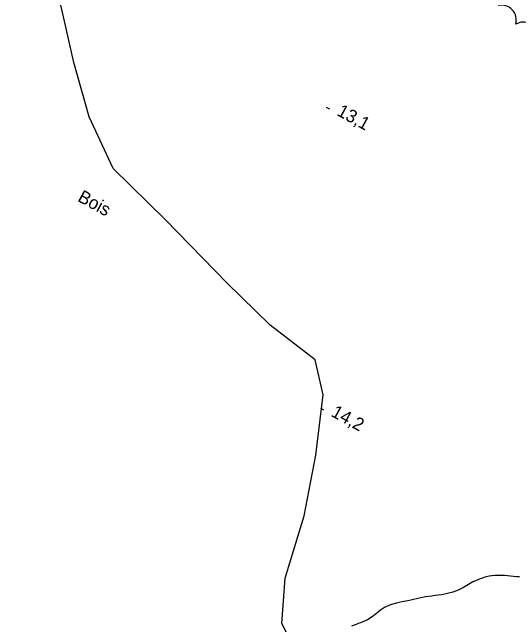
# Model space of a CAD drawing. Extents: x 219136 to 222520, y 5421589 to 5424530.
# Drawn here: x 220023.3 to 220141.1, y 5423381.3 to 5423523.8 of the extents above; entities that cross this region are included whole.
import ezdxf

# ---------------------------------------------------------------- set-up
doc = ezdxf.new("R2010")
doc.units = 0
for name, color, linetype in [('Level 2', 7, 'Continuous'), ('Level 22', 7, 'Continuous'), ('Level 3', 7, 'Continuous'), ('Level 44', 7, 'Continuous')]:
    doc.layers.add(name, color=color, linetype=linetype)

msp = doc.modelspace()

# ---------------------------------------------------------------- linework, layer by layer
at = {"layer": 'Level 2'}
msp.add_lwpolyline([(220141.32, 5423392.47), (220140.63, 5423392.51), (220139.92, 5423392.58), (220138.55, 5423392.68), (220137.81, 5423392.75), (220137.07, 5423392.79), (220136.31, 5423392.82), (220135.59, 5423392.79), (220134.88, 5423392.71), (220134.22, 5423392.62), (220133.58, 5423392.46), (220133, 5423392.29), (220132.44, 5423392.12), (220131.93, 5423391.93), (220131.42, 5423391.74), (220130.48, 5423391.3), (220129.46, 5423390.72), (220128.26, 5423390), (220127.66, 5423389.65), (220127.04, 5423389.36), (220126.43, 5423389.11), (220125.81, 5423388.94), (220124.52, 5423388.6), (220123.12, 5423388.32), (220122.4, 5423388.2), (220121.66, 5423388.1), (220120.91, 5423388), (220119.45, 5423387.8), (220118.05, 5423387.54), (220117.37, 5423387.36), (220116.68, 5423387.21), (220115.99, 5423387.06), (220115.33, 5423386.93), (220113.99, 5423386.63), (220113.31, 5423386.49), (220112.67, 5423386.34), (220111.5, 5423386.03), (220110.94, 5423385.83), (220109.92, 5423385.32), (220108.98, 5423384.69), (220108.03, 5423383.93), (220107.02, 5423383.17), (220105.94, 5423382.51), (220104.86, 5423382), (220104.32, 5423381.8), (220103.8, 5423381.61), (220103.28, 5423381.43), (220102.21, 5423381)], dxfattribs=at)
at = {"layer": 'Level 22'}
for points in [[(220035.31, 5423522.39), (220031.97, 5423536.87), (220028.14, 5423552.15), (220025.55, 5423560.07), (220023.73, 5423567.57), (220023.28, 5423570.2), (220023.28, 5423570.21)], [(220101.57, 5423359.15), (220098.08, 5423364.96), (220088.9, 5423376.02), (220085.97, 5423381.6), (220086.82, 5423392.18), (220091.21, 5423406.68), (220093.91, 5423420.75), (220095.65, 5423434.83), (220093.8, 5423442.93), (220083.32, 5423450.98), (220073.2, 5423460.85), (220058.91, 5423475.45), (220046.74, 5423487.46), (220041.18, 5423499.45), (220037.61, 5423512.06), (220035.31, 5423522.39)]]:
    msp.add_lwpolyline(points, dxfattribs=at)
at = {"layer": 'Level 3'}
for p, q in [((220096.36, 5423501.65), (220097.06, 5423501.26)), ((220095.02, 5423431.7), (220095.72, 5423431.31))]:
    msp.add_line(p, q, dxfattribs=at)
at = {"layer": 'Level 44'}
for centre, start, end in [((220137.1, 5423521.95), 343.2974, 103.2974), ((220142.25, 5423518.01), 2.0114, 122.0114)]:
    msp.add_arc(centre, 3.46, start, end, dxfattribs=at)

# ---------------------------------------------------------------- texts
at = {"layer": 'Level 3'}
for s, p in [('13,1', (220098.6, 5423499.91)), ('14,2', (220097.26, 5423429.95))]:
    msp.add_text(s, height=3, rotation=331.383, dxfattribs=at).set_placement(p)
at = {"layer": 'Level 44'}
msp.add_text('Bois', height=3, rotation=331.3547, dxfattribs=at).set_placement((220038.29, 5423479.95))

doc.saveas('drawing.dxf')
